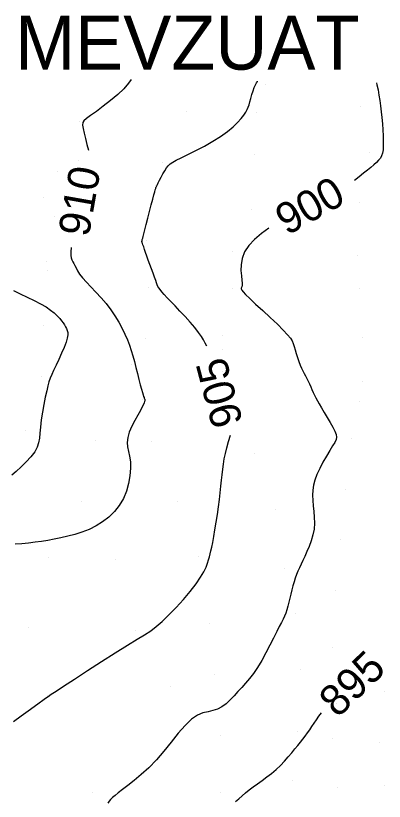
# Model space of a CAD drawing. Extents: x 400243 to 403697, y 4403637 to 4408083.
# Drawn here: x 402623.4 to 402712.3, y 4406378.5 to 4406567.9 of the extents above; entities that cross this region are included whole.
import ezdxf

# ---------------------------------------------------------------- set-up
doc = ezdxf.new("R2010")
doc.units = 0
doc.layers.add('HH_IC', color=7, linetype='Continuous')

msp = doc.modelspace()

# ---------------------------------------------------------------- linework, layer by layer
at = {"layer": 'HH_IC'}
for p, q in [((402683.56, 4406551.42), (402683.56, 4406551.42)), ((402706.65, 4406546.05), (402706.65, 4406546.05)), ((402664.66, 4406544.82), (402664.66, 4406544.82)), ((402681.45, 4406544.56), (402681.45, 4406544.56)), ((402638.72, 4406542.44), (402638.72, 4406542.44)), ((402681.04, 4406534.41), (402681.04, 4406534.41)), ((402708.61, 4406534.83), (402708.61, 4406534.83)), ((402638.64, 4406532.95), (402638.64, 4406532.95)), ((402658.67, 4406532.57), (402658.67, 4406532.57)), ((402633.56, 4406530.29), (402633.56, 4406530.29)), ((402657.08, 4406526.84), (402657.08, 4406526.84)), ((402629.96, 4406523.99), (402629.96, 4406523.99)), ((402706.18, 4406522.95), (402706.18, 4406522.95)), ((402680.15, 4406521.13), (402680.15, 4406521.13)), ((402632.62, 4406519.5), (402632.62, 4406519.5)), ((402654.98, 4406513.59), (402654.98, 4406513.59)), ((402675.77, 4406511.13), (402675.77, 4406511.13)), ((402705.93, 4406510.05), (402705.93, 4406510.05)), ((402630.9, 4406508.71), (402630.9, 4406508.71)), ((402630.94, 4406506.57), (402630.94, 4406506.57)), ((402655.48, 4406502.33), (402655.48, 4406502.33)), ((402675.66, 4406502.21), (402675.66, 4406502.21)), ((402706.37, 4406502.12), (402706.37, 4406502.12)), ((402630.11, 4406493.12), (402630.11, 4406493.12)), ((402673.21, 4406490.83), (402673.21, 4406490.83)), ((402654.61, 4406490.19), (402654.61, 4406490.19)), ((402706.92, 4406490.31), (402706.92, 4406490.31)), ((402673.28, 4406487.31), (402673.28, 4406487.31)), ((402651.3, 4406483.7), (402651.3, 4406483.7)), ((402673.23, 4406482.06), (402673.23, 4406482.06)), ((402629.49, 4406480.91), (402629.49, 4406480.91)), ((402707.07, 4406479.77), (402707.07, 4406479.77)), ((402653.91, 4406475.33), (402653.91, 4406475.33)), ((402706.23, 4406474.91), (402706.23, 4406474.91)), ((402676.73, 4406472.5), (402676.73, 4406472.5)), ((402625.75, 4406467.98), (402625.75, 4406467.98)), ((402642.53, 4406465.5), (402642.53, 4406465.5)), ((402656.24, 4406465.34), (402656.24, 4406465.34)), ((402704.3, 4406465.95), (402704.3, 4406465.95)), ((402680.93, 4406462.35), (402680.93, 4406462.35)), ((402702.88, 4406453.75), (402702.88, 4406453.75)), ((402662.36, 4406450.86), (402662.36, 4406450.86)), ((402639.13, 4406450.75), (402639.13, 4406450.75)), ((402685.94, 4406448.79), (402685.94, 4406448.79)), ((402701.83, 4406441.51), (402701.83, 4406441.51)), ((402667.43, 4406437.57), (402667.43, 4406437.57)), ((402631.29, 4406437.39), (402631.29, 4406437.39)), ((402647.44, 4406436.8), (402647.44, 4406436.8)), ((402688.23, 4406434.62), (402688.23, 4406434.62)), ((402700.57, 4406429.27), (402700.57, 4406429.27)), ((402690.75, 4406423.69), (402690.75, 4406423.69)), ((402670.21, 4406421.45), (402670.21, 4406421.45)), ((402626.52, 4406420.31), (402626.52, 4406420.31)), ((402652.28, 4406419.72), (402652.28, 4406419.72)), ((402699.72, 4406415.52), (402699.72, 4406415.52)), ((402692.15, 4406410.34), (402692.15, 4406410.34)), ((402671.29, 4406408.99), (402671.29, 4406408.99)), ((402660.62, 4406406.12), (402660.62, 4406406.12)), ((402700.62, 4406406.08), (402700.62, 4406406.08)), ((402631.07, 4406403.9), (402631.07, 4406403.9)), ((402700.74, 4406403.69), (402700.74, 4406403.69)), ((402712.22, 4406405.07), (402712.22, 4406405.07)), ((402700.63, 4406402.17), (402700.63, 4406402.17)), ((402672.85, 4406394.27), (402672.85, 4406394.27)), ((402691.46, 4406395.25), (402691.46, 4406395.25)), ((402699.69, 4406393.69), (402699.69, 4406393.69)), ((402711.1, 4406392.6), (402711.1, 4406392.6)), ((402690.18, 4406383.57), (402690.18, 4406383.57)), ((402701.09, 4406381.89), (402701.09, 4406381.89)), ((402712.28, 4406382.19), (402712.28, 4406382.19)), ((402641.89, 4406380.5), (402641.89, 4406380.5)), ((402672.71, 4406380.62), (402672.71, 4406380.62))]:
    msp.add_line(p, q, dxfattribs=at)
for points in [[(402651.21, 4406552.49), (402650.61, 4406551.62), (402649.48, 4406550.28), (402648, 4406548.86), (402646.28, 4406547.42), (402644.5, 4406546.05), (402642.83, 4406544.82), (402641.44, 4406543.83), (402640.44, 4406543.12), (402639.83, 4406542.59), (402639.53, 4406542.11), (402639.48, 4406541.53), (402639.61, 4406540.73), (402639.87, 4406539.61), (402640.2, 4406538.27), (402640.56, 4406536.84), (402640.9, 4406535.48)], [(402669.47, 4406488.21), (402669.1, 4406488.96), (402668.7, 4406489.72), (402668.19, 4406490.56), (402667.49, 4406491.54), (402666.55, 4406492.7), (402665.44, 4406493.99), (402664.22, 4406495.34), (402663, 4406496.67), (402661.84, 4406497.91), (402660.81, 4406498.99), (402659.94, 4406499.91), (402659.21, 4406500.69), (402658.63, 4406501.33), (402658.19, 4406501.85), (402657.88, 4406502.27), (402657.67, 4406502.63), (402657.51, 4406503.02), (402657.35, 4406503.48), (402657.15, 4406504.09), (402656.86, 4406504.88), (402656.51, 4406505.83), (402656.13, 4406506.86), (402655.73, 4406507.93), (402655.35, 4406508.97), (402655, 4406509.93), (402654.7, 4406510.79), (402654.45, 4406511.53), (402654.24, 4406512.15), (402654.07, 4406512.63), (402653.96, 4406512.96), (402653.88, 4406513.17), (402653.84, 4406513.3), (402653.82, 4406513.37), (402653.82, 4406513.43), (402653.83, 4406513.5), (402653.84, 4406513.58), (402653.86, 4406513.68), (402653.89, 4406513.79), (402653.91, 4406513.92), (402653.95, 4406514.07), (402654.01, 4406514.3), (402654.11, 4406514.69), (402654.27, 4406515.32), (402654.51, 4406516.27), (402654.85, 4406517.57), (402655.25, 4406519.11), (402655.67, 4406520.73), (402656.08, 4406522.3), (402656.43, 4406523.66), (402656.71, 4406524.69), (402656.91, 4406525.43), (402657.05, 4406525.93), (402657.14, 4406526.25), (402657.21, 4406526.45), (402657.26, 4406526.59), (402657.32, 4406526.72), (402657.41, 4406526.91), (402657.55, 4406527.19), (402657.77, 4406527.62), (402658.08, 4406528.23), (402658.46, 4406528.96), (402658.88, 4406529.76), (402659.32, 4406530.53), (402659.75, 4406531.2), (402660.16, 4406531.73), (402660.62, 4406532.17), (402661.25, 4406532.58), (402662.11, 4406533.06), (402663.32, 4406533.66), (402664.93, 4406534.45), (402666.83, 4406535.41), (402668.88, 4406536.48), (402670.92, 4406537.63), (402672.81, 4406538.8), (402674.44, 4406539.97), (402675.8, 4406541.1), (402676.9, 4406542.16), (402677.77, 4406543.12), (402678.43, 4406543.95), (402678.9, 4406544.65), (402679.23, 4406545.26), (402679.47, 4406545.83), (402679.66, 4406546.44), (402679.86, 4406547.14), (402680.09, 4406547.96), (402680.36, 4406548.87), (402680.64, 4406549.77), (402680.93, 4406550.59), (402681.21, 4406551.25), (402681.45, 4406551.71), (402681.66, 4406552.03), (402681.7, 4406552.11)], [(402710.4, 4406551.74), (402710.5, 4406551.25), (402710.76, 4406550.01), (402711, 4406548.75), (402711.2, 4406547.46), (402711.38, 4406546.13), (402711.54, 4406544.75), (402711.68, 4406543.33), (402711.81, 4406541.85), (402711.92, 4406540.38), (402712, 4406538.96), (402712.04, 4406537.65), (402712.03, 4406536.5), (402711.97, 4406535.55), (402711.84, 4406534.78), (402711.63, 4406534.13), (402711.33, 4406533.57), (402710.92, 4406533.04), (402710.41, 4406532.5), (402709.78, 4406531.94), (402709.05, 4406531.33), (402708.2, 4406530.66), (402707.25, 4406529.91), (402706.19, 4406529.08), (402705.06, 4406528.18)], [(402684.41, 4406516.64), (402682.63, 4406515.35), (402681, 4406513.95), (402679.62, 4406512.48), (402678.59, 4406510.95), (402677.99, 4406509.39), (402677.73, 4406507.87), (402677.71, 4406506.44), (402677.82, 4406505.18), (402677.94, 4406504.15), (402677.98, 4406503.4), (402677.97, 4406502.89), (402677.91, 4406502.56), (402677.83, 4406502.35), (402677.77, 4406502.18), (402677.76, 4406502.01), (402677.88, 4406501.76), (402678.2, 4406501.34), (402678.82, 4406500.69), (402679.83, 4406499.71), (402681.25, 4406498.37), (402682.96, 4406496.79), (402684.76, 4406495.11), (402686.48, 4406493.49), (402687.92, 4406492.08), (402688.96, 4406490.99), (402689.64, 4406490.16), (402690.06, 4406489.48), (402690.33, 4406488.85), (402690.55, 4406488.17), (402690.78, 4406487.36), (402691.06, 4406486.44), (402691.35, 4406485.49), (402691.67, 4406484.54), (402691.99, 4406483.67), (402692.31, 4406482.92), (402692.63, 4406482.26), (402692.94, 4406481.65), (402693.26, 4406481.07), (402693.58, 4406480.46), (402693.89, 4406479.82), (402694.21, 4406479.14), (402694.52, 4406478.44), (402694.83, 4406477.75), (402695.13, 4406477.08), (402695.43, 4406476.43), (402695.76, 4406475.78), (402696.13, 4406475.08), (402696.57, 4406474.28), (402697.12, 4406473.34), (402697.79, 4406472.24), (402698.51, 4406471.04), (402699.23, 4406469.82), (402699.87, 4406468.68), (402700.37, 4406467.7), (402700.67, 4406466.93), (402700.75, 4406466.3), (402700.64, 4406465.7), (402700.32, 4406465.02), (402699.81, 4406464.16), (402699.13, 4406463.04), (402698.33, 4406461.7), (402697.49, 4406460.24), (402696.7, 4406458.75), (402696.02, 4406457.29), (402695.53, 4406455.95), (402695.2, 4406454.69), (402695.03, 4406453.48), (402694.97, 4406452.28), (402695.02, 4406451.05), (402695.14, 4406449.75), (402695.29, 4406448.4), (402695.4, 4406447), (402695.44, 4406445.57), (402695.33, 4406444.14), (402695.06, 4406442.7), (402694.65, 4406441.3), (402694.15, 4406439.95), (402693.62, 4406438.7), (402693.09, 4406437.55), (402692.61, 4406436.54), (402692.19, 4406435.64), (402691.81, 4406434.8), (402691.45, 4406433.99), (402691.13, 4406433.16), (402690.81, 4406432.28), (402690.52, 4406431.37), (402690.23, 4406430.42), (402689.97, 4406429.44), (402689.71, 4406428.45), (402689.48, 4406427.46), (402689.25, 4406426.48), (402689.02, 4406425.54), (402688.78, 4406424.66), (402688.52, 4406423.85), (402688.23, 4406423.12), (402687.89, 4406422.39), (402687.48, 4406421.59), (402686.96, 4406420.62), (402686.33, 4406419.39), (402685.56, 4406417.86), (402684.68, 4406416.11), (402683.72, 4406414.26), (402682.72, 4406412.44), (402681.72, 4406410.76), (402680.74, 4406409.31), (402679.78, 4406408.06), (402678.84, 4406406.96), (402677.91, 4406405.94), (402676.98, 4406404.94), (402676.05, 4406403.92), (402675.1, 4406402.93), (402674.12, 4406402.02), (402673.12, 4406401.25), (402672.06, 4406400.68), (402670.96, 4406400.35), (402669.79, 4406400.1), (402668.55, 4406399.79), (402667.21, 4406399.23), (402665.78, 4406398.27), (402664.24, 4406396.8), (402662.6, 4406394.91), (402660.89, 4406392.78), (402659.11, 4406390.58), (402657.3, 4406388.47), (402655.46, 4406386.58), (402653.66, 4406384.93), (402651.96, 4406383.52), (402650.43, 4406382.33), (402649.13, 4406381.34), (402648.11, 4406380.55), (402647.33, 4406379.91), (402646.74, 4406379.39), (402646.28, 4406378.93), (402645.91, 4406378.51), (402645.57, 4406378.08)], [(402636.76, 4406512.04), (402636.65, 4406510.94), (402636.66, 4406510.11), (402636.76, 4406509.48), (402636.94, 4406509), (402637.16, 4406508.58), (402637.4, 4406508.15), (402637.64, 4406507.66), (402637.92, 4406507.09), (402638.29, 4406506.41), (402638.8, 4406505.62), (402639.5, 4406504.71), (402640.42, 4406503.67), (402641.52, 4406502.52), (402642.72, 4406501.26), (402643.96, 4406499.91), (402645.16, 4406498.48), (402646.29, 4406497.01), (402647.31, 4406495.5), (402648.22, 4406493.99), (402649.03, 4406492.51), (402649.73, 4406491.09), (402650.31, 4406489.76), (402650.8, 4406488.47), (402651.23, 4406487.2), (402651.62, 4406485.9), (402652, 4406484.54), (402652.38, 4406483.1), (402652.75, 4406481.63), (402653.11, 4406480.21), (402653.43, 4406478.93), (402653.71, 4406477.85), (402653.94, 4406477.04), (402654.11, 4406476.47), (402654.23, 4406476.08), (402654.33, 4406475.83), (402654.4, 4406475.66), (402654.45, 4406475.54), (402654.49, 4406475.43), (402654.51, 4406475.33), (402654.51, 4406475.21), (402654.5, 4406475.07), (402654.46, 4406474.88), (402654.37, 4406474.6), (402654.19, 4406474.18), (402653.89, 4406473.57), (402653.44, 4406472.72), (402652.81, 4406471.61), (402652.09, 4406470.31), (402651.38, 4406468.91), (402650.78, 4406467.5), (402650.39, 4406466.18), (402650.27, 4406465.01), (402650.38, 4406463.94), (402650.6, 4406462.86), (402650.85, 4406461.7), (402651.04, 4406460.35), (402651.08, 4406458.77), (402650.94, 4406457), (402650.62, 4406455.14), (402650.09, 4406453.27), (402649.34, 4406451.47), (402648.36, 4406449.82), (402647.18, 4406448.33), (402645.83, 4406447), (402644.34, 4406445.85), (402642.75, 4406444.87), (402641.07, 4406444.05), (402639.35, 4406443.39), (402637.62, 4406442.85), (402635.91, 4406442.4), (402634.25, 4406442.02), (402632.66, 4406441.69), (402631.12, 4406441.4), (402629.6, 4406441.15), (402628.07, 4406440.94), (402626.5, 4406440.75), (402624.86, 4406440.6), (402623.21, 4406440.46)], [(402622.83, 4406501.66), (402624.47, 4406500.86), (402626.18, 4406500.06), (402627.85, 4406499.25), (402629.39, 4406498.46), (402630.69, 4406497.68), (402631.78, 4406496.94), (402632.67, 4406496.22), (402633.39, 4406495.55), (402633.98, 4406494.93), (402634.46, 4406494.36), (402634.85, 4406493.84), (402635.16, 4406493.36), (402635.41, 4406492.91), (402635.62, 4406492.47), (402635.79, 4406492.03), (402635.91, 4406491.53), (402635.92, 4406490.93), (402635.8, 4406490.16), (402635.52, 4406489.17), (402635.05, 4406487.92), (402634.44, 4406486.51), (402633.77, 4406485.04), (402633.11, 4406483.62), (402632.52, 4406482.37), (402632.05, 4406481.36), (402631.69, 4406480.49), (402631.4, 4406479.64), (402631.13, 4406478.68), (402630.85, 4406477.48), (402630.52, 4406475.94), (402630.17, 4406474.17), (402629.83, 4406472.29), (402629.53, 4406470.43), (402629.32, 4406468.73), (402629.19, 4406467.28), (402629.09, 4406466.04), (402628.91, 4406464.92), (402628.56, 4406463.85), (402627.96, 4406462.74), (402627.05, 4406461.54), (402625.91, 4406460.3), (402624.67, 4406459.1), (402623.47, 4406458.03), (402622.42, 4406457.15)], [(402622.81, 4406397.7), (402624.73, 4406399.09), (402626.42, 4406400.31), (402627.86, 4406401.35), (402629.04, 4406402.2), (402629.94, 4406402.86), (402630.59, 4406403.34), (402631.18, 4406403.77), (402631.94, 4406404.29), (402633.11, 4406405.07), (402634.92, 4406406.26), (402637.52, 4406407.95), (402640.67, 4406409.99), (402644.06, 4406412.18), (402647.38, 4406414.29), (402650.32, 4406416.13), (402652.64, 4406417.55), (402654.44, 4406418.66), (402655.93, 4406419.63), (402657.29, 4406420.63), (402658.71, 4406421.85), (402660.33, 4406423.41), (402662.08, 4406425.23), (402663.84, 4406427.17), (402665.48, 4406429.11), (402666.89, 4406430.92), (402667.96, 4406432.49), (402668.74, 4406433.82), (402669.28, 4406434.95), (402669.65, 4406435.91), (402669.91, 4406436.72), (402670.12, 4406437.43), (402670.31, 4406438.12), (402670.48, 4406438.86), (402670.67, 4406439.76), (402670.89, 4406440.89), (402671.14, 4406442.32), (402671.43, 4406443.98), (402671.73, 4406445.79), (402672.02, 4406447.66), (402672.29, 4406449.5), (402672.52, 4406451.25), (402672.72, 4406452.89), (402672.89, 4406454.43), (402673.04, 4406455.88), (402673.18, 4406457.24), (402673.33, 4406458.53), (402673.49, 4406459.79), (402673.68, 4406461.04), (402673.94, 4406462.34), (402674.27, 4406463.73), (402674.69, 4406465.21), (402675.16, 4406466.73)], [(402676.35, 4406378.45), (402677.18, 4406379.12), (402678, 4406379.81), (402678.83, 4406380.51), (402679.72, 4406381.24), (402680.67, 4406381.97), (402681.71, 4406382.73), (402682.81, 4406383.52), (402683.94, 4406384.35), (402685.08, 4406385.22), (402686.18, 4406386.15), (402687.23, 4406387.14), (402688.21, 4406388.16), (402689.12, 4406389.19), (402689.96, 4406390.18), (402690.73, 4406391.12), (402691.43, 4406391.97), (402692.06, 4406392.76), (402692.65, 4406393.5), (402693.21, 4406394.23), (402693.75, 4406394.96), (402694.28, 4406395.73), (402694.82, 4406396.52), (402695.37, 4406397.33), (402695.93, 4406398.16), (402696.51, 4406398.99), (402697.1, 4406399.82)]]:
    msp.add_lwpolyline(points, dxfattribs=at)

# ---------------------------------------------------------------- texts
msp.add_text('MEVZUAT ', height=13).set_placement((402623.24, 4406554.89))
for s, rotation, p in [('910', 79.982, (402640.97, 4406514.34)), ('900', 29.2058, (402688.79, 4406514.79)), ('905', 104.8398, (402678.22, 4406469.82)), ('895', 44.0773, (402701.03, 4406398.41))]:
    msp.add_text(s, height=7.5, rotation=rotation, dxfattribs=at).set_placement(p)

doc.saveas('drawing.dxf')
